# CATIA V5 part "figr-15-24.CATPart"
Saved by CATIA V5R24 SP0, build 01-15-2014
Part number: Part1
Bounding box of the stored display mesh (mm): x -50 to 50, y -25 to 26, z -24 to 1
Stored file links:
  D:\KAVITA\CATIA V5-6R2014 Project_ Kavita\CATIA V5-6R2014_partfiles\Partfiles\c15_catia_v5-6r2014_prt\figr-15-24.CATPart
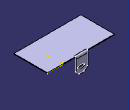
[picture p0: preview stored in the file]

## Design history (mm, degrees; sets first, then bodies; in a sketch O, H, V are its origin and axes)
SheetMetalParameters1: Thickness 1, BendRadius 2, KFactor 0.400515 {= log(min(100,max(20*SheetMetalParameters1.BendRadius,SheetMetalParameters1.Thickness)/SheetMetalParameters1.Thickness))/log(100)/2}, ReliefRadialLength 1, ReliefAxialLength 2, MinimumBendRadius 0
Body1 (main body)
  Sketch1 on xy-plane, origin (0, 0, 0), H (1, 0, 0), V (0, 1, 0)
    line L1 (-50, 25) -> (50, 25)
    line L2 (50, 25) -> (50, -25)
    line L3 (50, -25) -> (-50, -25)
    line L4 (-50, -25) -> (-50, 25)
    length L1 = 100
    distance V L2 = 50
    length L2 = 50
    distance H L3 = 25
    horizontal: L1 H, L3 H
    vertical: L2 V, L4 V
  Wall1: Thickness 1, Profile Sketch1
  Sketch2 on face of Wall1, origin (50, 25, 0), H (-1, 0, 0), V (0, 0, 1)
    line L1 (42.3549, 1) -> (42.3549, -19)
    point P2 (42.3549, -19)
    line L2 (42.3549, -19) -> (47.3549, -24)
    point P3 (47.3549, -24)
    line L3 (47.3549, -24) -> (54.3549, -24)
    point P4 (54.3549, -24)
    line L4 (54.3549, -24) -> (59.3549, -19)
    point P5 (59.3549, -19)
    line L5 (59.3549, -19) -> (59.3549, 1)
    line L6 (59.3549, 1) -> (42.3549, 1)
    reference projected line E1 (100, 1) -> (0, 1) from edge [face of Wall1 | face of Wall1]
    ellipse A1 centre (50.1164, -15.2153) semi-axes 5.0583, 2.1402 rotation 0
    length L5 = 20
    length L1 = 20
    length L3 = 7
    distance P4 L5 = 5
    distance P2 P3 H = 5
    distance L3 P5 = 5
    vertical: L1 V, L5 V
    horizontal: L3 H, L6 H
    coincidence: L6 E1
    parallelism: A1 L3
  d_NewWallOnEdge1: NewWallOnEdge_Edge edge [face of Wall1 | face of Wall1], NewWallOnEdge_WallProfile Sketch2, NewWallOnEdge_Length 100, NewWallOnEdge_HeightLimitOffset 0, NewWallOnEdge_WidthOffset1 0, NewWallOnEdge_WidthOffset2 0, NewWallOnEdge_Angle 0, NewWallOnEdge_BendRadiusValue 2 {= SheetMetalParameters1.BendRadius}, NewWallOnEdge_BendTable SheetMetalParameters1, KFacteur 0.400515 {= log(min(100,max(20*d_NewWallOnEdge1.Radius,SheetMetalParameters1.Thickness)/SheetMetalParameters1.Thickness))/log(100)/2}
